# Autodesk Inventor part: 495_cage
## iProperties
Author: Administrator
Shininess: 64.0
Angle Display Precision: 2
Document Length Units: 11272
Document Angle Units: 11286
Document Time Units: 11279
Document Mass Units: 11290
Document Length Units Precision: 3
Document Angle Units Precision: 2
Compacted: True
PropertySet Name: _Private Model Information
Created: 2002-03
Part Number: 495_cage
Material: Stainless Steel, 440C
Document SubType Name: Modeling
Designer: Administrator
Control State: 0
Master: False
Checked Out: False
PropertySet Name: Design Tracking Control
Density: 0.0
Volumn: 0.0
Area: 0.0
PropertySet Name: Model Information
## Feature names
1. Revolution1
2. Extrusion2
3. Circular Pattern2
